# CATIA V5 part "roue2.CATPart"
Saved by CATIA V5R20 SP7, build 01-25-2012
Part number: roue2
Bounding box of the stored display mesh (mm): x 366 to 535.972, y -37.5 to 30, z -319.972 to 220
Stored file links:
  D:\thinkmotion-MPB\Dropbox\Pack 1 sylvain\CFAO_2010_yyang\yyang\CFAO_2010_yyang\roue2.CATPart
  D:\thinkmotion-MPB\Dropbox\Pack 1 sylvain\CFAO_2010_yyang\yyang\CFAO_2010_yyang\yyang.CATProduct
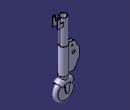
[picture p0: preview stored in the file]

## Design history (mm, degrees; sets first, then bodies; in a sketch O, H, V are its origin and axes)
External parameters (linked from other documents)
  `External.angle de l'antiboue` = 40 deg
  `External.rayon1 de l'antiboue` = 30 mm
  `External.rayon2 de l'antiboue` = 25 mm
  `External.epaisseur du pivot` = 2 mm
  `External.largeur du support de la petale` = 100 mm
  `External.demi-distance entre les des pivot` = 9 mm
  `External.longeur du support de la petale` = 180 mm
  `External.rayon du trou des liaisons` = 5 mm
  `External.longueur de chanfrain` = 35 mm
  `External.demi_largeur de la partie verticale` = 10 mm
  `External.demi_largeur de la partie horizontale` = 12.5 mm
  `External.demi_distance entre les oreilles` = 15 mm
  `External.epaisseur de l'oreille` = 3 mm
  `External.haut du support de la petale` = 275 mm
  `External.rayon de la liaison du petale` = 10 mm
  `External.epaisseur du roue` = 32 mm
  `External.rayon plus grande de la boite` = 35 mm
  `External.rayon plus petite de la boite` = 15 mm
  `External.epaisseur de la boite` = 7.5 mm
Set1
  Plane1: linked copy from another document
  Point1 to Point3: linked copy from another document
  Line1: linked copy from another document
  Point4: linked copy from another document
  Point5: linked copy from another document
  Plane2: linked copy from another document
  Point6: linked copy from another document
  Point7: linked copy from another document
  Line2: linked copy from another document
  Plane3: linked copy from another document
  Point8: linked copy from another document
  Point9: linked copy from another document
  Plane4: linked copy from another document
  Point10: linked copy from another document
  Line3: linked copy from another document
  Line4: linked copy from another document
  Point11: linked copy from another document
  Line5: linked copy from another document
  Line6: linked copy from another document
  Point12: linked copy from another document
Body1 (main body)
  Sketch1 on Plane1, origin (466, 0, 0), H (0, 1, 0), V (0, 0, 1)
    construction line L1 (0, -196) -> (0, -304)
    point P1 (0, -196)
    point P2 (0, -304)
    line L2 (16, -196) -> (16, -250)
    line L3 (-16, -250) -> (-16, -196)
    arc A1 centre (0, -196) radius 16 from (-16, -196) to (16, -196) cw
    point P4 (-16, -304)
    reference projected point E1 (0, -196) from Point1
    reference projected point E2 (0, -304) from Point2
    reference projected point E3 (16, -250) from Point3
    line L4 (16, -250) -> (-16, -250)
    vertical: L1 V
    tangency: A1 L2, A1 L3
    coincidence: P1 E1, P2 E2, L2 E3
    horizontal: L4 H
  Shaft1: profile Sketch1, axis Line1, angle 360
  Sketch2 on Plane1, origin (466, 0, 0), H (0, 1, 0), V (0, 0, 1)
    arc A1 centre (0, -196) radius 30 from (30, -196) to (-30, -196) ccw
    point P1 (0, -196)
    reference projected point E1 (0, -196) from Point1
    reference projected point E2 (0, -166) from Point4
    arc A2 centre (0, -196) radius 25 from (25, -196) to (-25, -196) ccw
    point P2 (0, -196)
    reference projected point E3 (0, -196) from Point1
    reference projected point E4 (0, -171) from Point5
    line L1 (-25, -196) -> (-30, -196)
    line L2 (25, -196) -> (30, -196)
    point P5 (25, -196)
    coincidence: P1 E1, A1 E2, P2 E3, A2 E4, P5 L1
    horizontal: L1 H, L2 H
  Shaft2: profile Sketch2, axis Line1, angle 40 {= `External.angle de l'antiboue`}, second angle 40 {= `External.angle de l'antiboue`}
  Sketch3 on Plane2, origin (0, 0, 0), H (-1, 0, 0), V (0, 0, 1)
    circle A1 centre (-466, -250) radius 5
    point P1 (-466, -250)
    reference projected point E1 (-466, -250) from Point6
    reference projected point E2 (-466, -245) from Point7
    coincidence: P1 E1, A1 E2
  Pad1: profile Sketch3, direction (0, 1, 0), length 25 {= `External.rayon2 de l'antiboue`}, mirrored extent
  Sketch4 on start face of Pad1, origin (0, -25, 0), H (1, 0, 0), V (0, 0, 1)
    arc A1 centre (466, -250) radius 54 from (485.0629, -199.4767) to (446.9371, -199.4767) ccw
    point P1 (466, -250)
    reference projected point E1 (466, -250) from Point6
    reference projected point E2 (466, -196) from Point1
    arc A2 centre (466, -250) radius 10 from (456.1519, -251.7365) to (475.8481, -251.7365) ccw
    point P2 (466, -250)
    reference projected point E3 (466, -250) from Point6
    line L1 (446.9371, -199.4767) -> (456.1519, -251.7365)
    line L2 (485.0629, -199.4767) -> (475.8481, -251.7365)
    reference projected line E4 (466, -250) -> (466, 200) from Line2
    reference projected line E5 (466, -250) -> (466, 200) from Line2
    radius A2 = 10
    angle L2 E4 = 10
    angle L1 E5 = 10
    coincidence: P1 E1, A1 E2, P2 E3
    tangency: L2 A2, L1 A2
  Pad2: profile Sketch4, direction (0, -1, 0), length 5 {= `External.rayon1 de l'antiboue`-`External.rayon2 de l'antiboue`}
  Mirror1: of Pad2, about Plane2
  Sketch5 on Plane4, origin (0, 0, 25), H (1, 0, 0), V (0, 1, 0)
    arc A1 centre (466, 0) radius 24 from (443.7514, -9) to (443.7514, 9) ccw
    point P1 (466, 0)
    reference projected point E1 (466, 0) from Point2
    reference projected point E2 (490, 0) from Point8
    point P2 (466, 0)
    reference projected point E3 (466, 0) from Point7
    line L1 (442.4416, 11) -> (366, 11)
    line L2 (366, 11) -> (366, 9)
    line L3 (366, 9) -> (443.7514, 9)
    line L4 (442.4416, -11) -> (366, -11)
    line L5 (366, -11) -> (366, -9)
    line L6 (366, -9) -> (443.7514, -9)
    reference intersected line E4 through (0, 0) direction (-1, 0) from Plane2
    reference intersected line E5 through (0, 0) direction (-1, 0) from Plane2
    arc A2 centre (466, 0) radius 26 from (442.4416, -11) to (442.4416, 11) ccw
    reference projected line E6 (466, -40) -> (466, 0) from Line5
    reference projected line E7 (466, 0) -> (466, 40) from Line6
    distance L3 L1 = 2 {= `External.epaisseur du pivot`}
    distance L6 L4 = 2 {= `External.epaisseur du pivot`}
    distance L3 E4 = 9 {= `External.demi-distance entre les des pivot`}
    distance L6 E5 = 9 {= `External.demi-distance entre les des pivot`}
    distance A2 A1 = 2 {= `External.epaisseur du pivot`}
    distance E6 L5 = 100 {= `External.largeur du support de la petale`}
    distance E7 L2 = 100 {= `External.largeur du support de la petale`}
    coincidence: P1 E1, A1 E2, P2 E3
    horizontal: L1 H, L3 H, L4 H, L6 H
    vertical: L2 V, L5 V
  Pad3: profile Sketch5, direction (0, 0, -1), length 180 {= `External.longeur du support de la petale`}
  Sketch6 on Plane2, origin (0, 0, 0), H (-1, 0, 0), V (0, 0, 1)
    circle A1 centre (-416, 0) radius 5
    point P1 (-416, 0)
    reference projected point E1 (-416, 0) from Point10
    reference projected point E2 (-416, 0) from Point10
    distance A1 E2 = 5 {= `External.rayon du trou des liaisons`}
    coincidence: P1 E1
  Pocket1: profile Sketch6, direction (0, -1, 0), up to face of Pad3 from Sketch5.L4, opposite side up to face of Pad3 from Sketch5.L1
  Sketch7 on Plane2, origin (0, 0, 0), H (-1, 0, 0), V (0, 0, 1)
    line L1 (-526, 210) -> (-526, 150)
    line L2 (-506, 210) -> (-506, 175)
    line L3 (-506, 175) -> (-466, 175)
    point P1 (-466, 175)
    line L4 (-526, 150) -> (-466, 150)
    point P2 (-466, 150)
    reference projected line E1 (-516, 162.5) -> (-516, 210) from Line3
    reference projected line E2 (-516, 162.5) -> (-516, 210) from Line3
    reference projected line E3 (-466, 162.5) -> (-511, 162.5) from Line4
    reference projected line E4 (-466, 162.5) -> (-511, 162.5) from Line4
    reference projected line E5 (-466, -250) -> (-466, 200) from Line2
    reference projected line E6 (-466, -250) -> (-466, 200) from Line2
    arc A1 centre (-516, 210) radius 10 from (-506, 210) to (-526, 210) ccw
    point P5 (-516, 210)
    reference projected point E7 (-516, 210) from Point11
    circle A2 centre (-516, 210) radius 5
    point P8 (-516, 210)
    reference projected point E8 (-516, 210) from Point11
    reference projected point E9 (-516, 210) from Point11
    line L5 (-466, 175) -> (-466, 150)
    distance L2 E1 = 10 {= `External.demi_largeur de la partie verticale`}
    distance L1 E2 = 10 {= `External.demi_largeur de la partie verticale`}
    distance L3 E3 = 12.5 {= `External.demi_largeur de la partie horizontale`}
    distance L4 E4 = 12.5 {= `External.demi_largeur de la partie horizontale`}
    distance A2 E9 = 5 {= `External.rayon du trou des liaisons`}
    vertical: L1 V, L2 V, L5 V
    horizontal: L3 H, L4 H
    coincidence: P1 E5, P2 E6, P5 E7, P8 E8
    tangency: A1 L2
  Pad4: profile Sketch7, direction (0, 1, 0), length 18 {= `External.demi_distance entre les oreilles`+`External.epaisseur de l'oreille`}, mirrored extent
  Sketch8 on Plane2, origin (0, 0, 0), H (-1, 0, 0), V (0, 0, 1)
    line L1 (-526, 220) -> (-466, 220)
    line L2 (-466, 220) -> (-466, 150)
    line L3 (-466, 150) -> (-526, 150)
    line L4 (-526, 150) -> (-526, 220)
    reference projected line E1 (-466, -250) -> (-466, 200) from Line2
    reference projected line E2 (-526, 210) -> (-526, 150) from edge [face of Pad4 from Sketch7.L1 | end face of Pad4]
    reference projected arc E3 centre (-516, 210) radius 10 from (-506, 210) to (-526, 210) ccw from edge [face of Pad4 from Sketch7.A1 | end face of Pad4]
    reference projected line E4 (-521, 150) -> (-466, 150) from edge [face of Pad4 from Sketch7.L4 | end face of Pad4]
    horizontal: L1 H, L3 H
    vertical: L2 V, L4 V
    coincidence: L2 E1, L4 E2, E4 L3
    tangency: L1 E3
  Pocket2: profile Sketch8, direction (0, -1, 0), length 15 {= `External.demi_distance entre les oreilles`}, mirrored extent
  Sketch9 on Plane3, origin (0, 0, 200), H (1, 0, 0), V (0, 1, 0)
    circle A1 centre (466, 0) radius 21
    point P1 (466, 0)
    reference projected point E1 (466, 0) from Point7
    reference projected point E2 (487, 0) from Point9
    circle A2 centre (466, 0) radius 24
    point P2 (466, 0)
    reference projected point E3 (466, 0) from Point7
    reference projected point E4 (490, 0) from Point8
    coincidence: P1 E1, A1 E2, P2 E3, A2 E4
  Pad5: profile Sketch9, direction (0, 0, -1), up to face of Shaft2 from Sketch2.A1
  Sketch10 on Plane3, origin (0, 0, 200), H (1, 0, 0), V (0, 1, 0)
    circle A1 centre (466, 0) radius 21
    point P1 (466, 0)
    reference projected point E1 (466, 0) from Point7
    reference projected point E2 (487, 0) from Point9
    reference projected point E3 (487, 0) from Point9
    coincidence: P1 E1, A1 E2, A1 E3
  Pocket3: profile Sketch10, direction (0, 0, -1), up to face of Pad4 from Sketch7.L4
  Chamfer1: length 35 {= `External.longueur de chanfrain`}, angle 60, on edge [face of Pad3 from Sketch5.L5 | start face of Pad3]; edge [face of Pad3 from Sketch5.L2 | start face of Pad3]; edge [end face of Pad3 | face of Pad3 from Sketch5.L2]; edge [end face of Pad3 | face of Pad3 from Sketch5.L5]
  Sketch11 on face of Pad3 from Sketch5.L4, origin (418.982, -11, -55.505), H (1, 0, 0), V (0, 0, 1)
    point P1 (-12.982, 10.505)
    reference projected point E1 (-12.982, 10.505) from Point12
    coincidence: P1 E1
  Hole1: placed by Sketch11, at (406, -11, -45) direction (0, 1, 0), diameter 20 {= `External.rayon de la liaison du petale`*2}, up to face of Pad3 from Sketch5.L1
  Sketch12 on Plane5, origin (0, -30, 0), H (-1, 0, 0), V (0, 0, 1)
    arc A1 centre (-406, -45) radius 35 from (-373.4773, -57.9335) to (-440.3638, -38.3569) ccw
    point P1 (-406, -45)
    reference projected point E1 (-406, -45) from Point12
    reference projected point E2 (-406, -45) from Point12
    arc A2 centre (-466, -250) radius 15 from (-480.7273, -247.153) to (-452.0617, -255.5429) ccw
    point P2 (-466, -250)
    reference projected point E3 (-466, -250) from Point6
    reference projected point E4 (-466, -250) from Point6
    line L1 (-452.0617, -255.5429) -> (-373.4773, -57.9335)
    line L2 (-480.7273, -247.153) -> (-440.3638, -38.3569)
    distance A1 E2 = 35 {= `External.rayon plus grande de la boite`}
    distance A2 E4 = 15 {= `External.rayon plus petite de la boite`}
    coincidence: P1 E1, P2 E3
    tangency: L1 A1, L2 A1, L1 A2, L2 A2
  Pad6: profile Sketch12, direction (0, -1, 0), length 7.5 {= `External.epaisseur de la boite`}
  Sketch13 on end face of Pad6, origin (416.7469, -37.5, -31.9316), H (1, 0, 0), V (0, 0, 1)
    point P1 (-10.7469, -13.0684)
    reference projected point E1 (-10.7469, -13.0684) from Point12
    coincidence: P1 E1
  Hole2: placed by Sketch13, at (406, -37.5, -45) direction (0, 1, 0), diameter 20 {= `External.rayon de la liaison du petale`*2}, up to start face of Pad6
  Sketch14 on start face of Pad6, origin (0, -30, 0), H (-1, 0, 0), V (0, 0, 1)
    arc A1 centre (-406, -45) radius 35 from (-373.4773, -57.9335) to (-440.997, -44.5423) ccw
    point P1 (-406, -45)
    reference projected point E1 (-406, -45) from Point12
    reference projected arc E2 centre (-406, -45) radius 35 from (-373.4773, -57.9335) to (-440.3638, -38.3569) ccw from edge [end face of Pad6 | face of Pad6 from Sketch12.A1]
    line L1 (-412.0783, -155) -> (-373.4773, -57.9335)
    point P2 (-412.0783, -155)
    reference projected line E3 (-452.0617, -255.5429) -> (-373.4773, -57.9335) from edge [end face of Pad6 | face of Pad6 from Sketch12.L1]
    reference projected line E4 (-366, -155) -> (-442.4416, -155) from edge [end face of Pad3 | face of Pad3 from Sketch5.L4]
    line L2 (-412.0783, -155) -> (-415.3068, -155)
    arc A2 centre (-406, -45) radius 32 from (-376.265, -56.8249) to (-437.9967, -44.5423) ccw
    line L3 (-440.997, -44.5423) -> (-437.9967, -44.5423)
    line L4 (-415.3068, -155) -> (-376.265, -56.8249)
    distance A2 A1 = 3
    coincidence: P1 E1, E3 L1, P2 E4
    tangency: A1 E2, L1 A1, L4 A2
    horizontal: L2 H, L3 H
    parallelism: L4 L1
  Pad7: profile Sketch14, direction (0, 1, 0), length 19 {= `External.rayon1 de l'antiboue`-`External.demi-distance entre les des pivot` -`External.epaisseur du pivot`}
  Plane5: type Offset, RefPlane Plane2, Offset 30 {= `External.rayon1 de l'antiboue`}, reversed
